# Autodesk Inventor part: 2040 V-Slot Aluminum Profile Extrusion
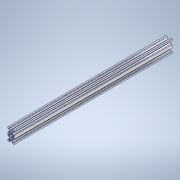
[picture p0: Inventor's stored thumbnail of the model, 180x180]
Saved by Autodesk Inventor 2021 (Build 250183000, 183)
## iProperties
Created: 2025-12
Part Number: 2040 V-Slot Aluminum Profile Extrusion
Material: Generic
Description: STEP AP214
Document SubType Name: Modeling
Designer: hp
Density: 1 g/cm^3
Appearance: Default
Title: Aluminium profile 2040 500mm.STEP
Revision Number: ANY
Sending System: SolidWorks 2024
Preprocessor: SwSTEP 2.0
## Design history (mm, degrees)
feature "Cut-Extrude1"
body "Solid1"
